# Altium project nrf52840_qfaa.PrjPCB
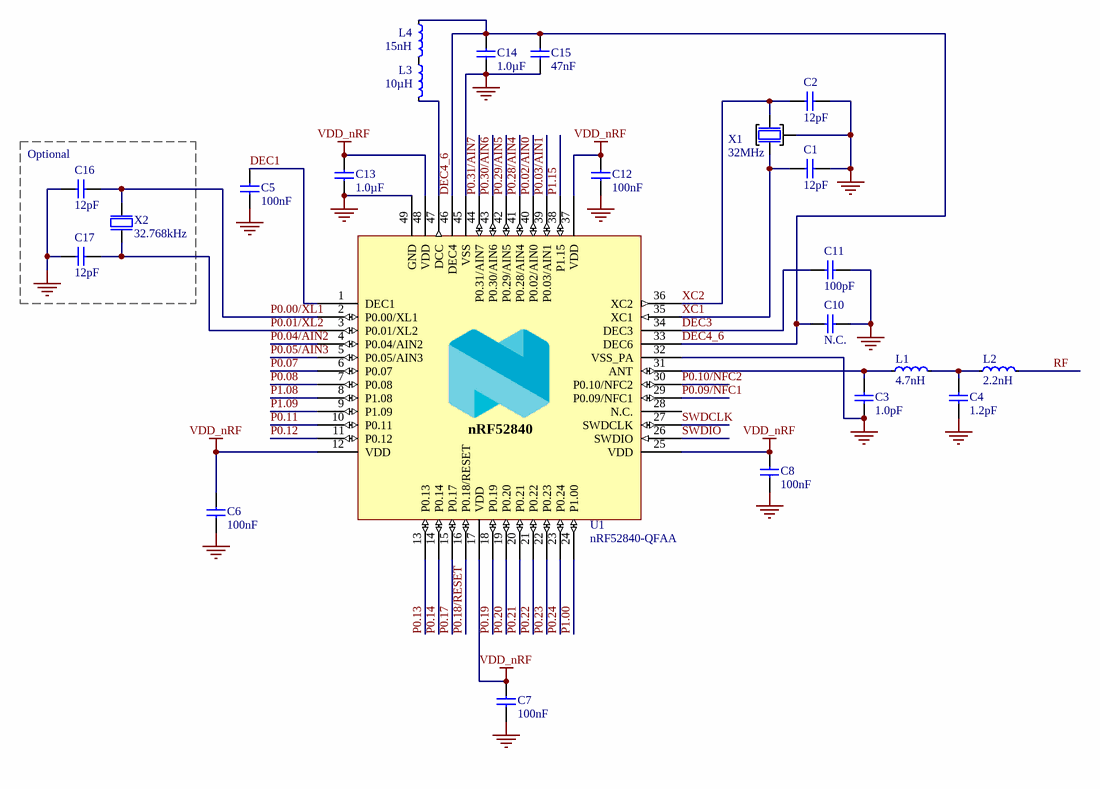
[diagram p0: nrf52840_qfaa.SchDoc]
1 sheet, 23 parts. Net scope: global (net labels, ports and power ports of the same name join across sheets).
Board file: nrf52840_qfaa.PcbDoc

## Sheet nrf52840_qfaa.SchDoc
size A4; Revision: 1.0; SheetNumber: 1; SheetTotal: 1; DrawnBy: RUBR; DocumentSize: A4; Device: nRF52840-QFAA; RefLayoutTitle: Reference Layout

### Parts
C1  12pF  [CAPC0603X03L_C]
C2  12pF  [CAPC0603X03L_C]
C3  1.0pF  [CAPC0603X03L_C]
C4  1.2pF  [CAPC0603X03L_C]
C5  100nF  [CAPC0603X03L_C]
C6  100nF  [CAPC0603X03L_C]
C7  100nF  [CAPC0603X03L_C]
C8  100nF  [CAPC0603X03L_C]
C10  N.C.  [CAPC0603X03L_C_NC]
C11  100pF  [CAPC0603X03L_C]
C12  100nF  [CAPC0603X03L_C]
C13  1.0µF  [CAPC1005X04L]
C14  1.0µF  [CAPC1005X04L]
C15  47nF  [CAPC0603X03L_C]
C16  12pF  [CAPC0603X03L_C]
C17  12pF  [CAPC0603X03L_C]
L1  4.7nH  [INDC0603X03L_C]
L2  2.2nH  [INDC0603X03L_C]
L3  10µH  [INDC1608X06L]
L4  15nH  [INDC1005X04L]
U1  nRF52840-QFAA  [QFN40P600X600X90-48N]
X1  32MHz  [XTAL_2016_NT]
X2  32.768kHz  [XTAL_2012]

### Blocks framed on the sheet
Optional: C16 C17 X2

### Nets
GND: C1.2 C2.2 C3.1 C4.1 C5.2 C6.2 C7.2 C8.2 C10.1 C11.2 C12.2 C13.2 C14.1 C15.2 C16.2 C17.2 U1.32(VSS_PA) U1.45(VSS) U1.49(GND) X1.2(GND)
VDD_nRF: C6.1 C7.1 C8.1 C12.1 C13.1 U1.12(VDD) U1.17(VDD) U1.25(VDD) U1.37(VDD) U1.48(VDD)
DEC1: C5.1 U1.1(DEC1)
DEC3: C11.1 U1.34(DEC3)
DEC4_6: C10.2 C14.2 C15.1 L4.1 U1.33(DEC6) U1.46(DEC4)
P0.00/XL1: C16.1 U1.2(P0.00/XL1) X2.1(inp)
P0.01/XL2: C17.1 U1.3(P0.01/XL2) X2.2(out)
P0.02/AIN0: U1.40(P0.02/AIN0)
P0.03/AIN1: U1.39(P0.03/AIN1)
P0.04/AIN2: U1.4(P0.04/AIN2)
P0.05/AIN3: U1.5(P0.05/AIN3)
P0.07: U1.6(P0.07)
P0.08: U1.7(P0.08)
P0.09/NFC1: U1.29(P0.09/NFC1)
P0.10/NFC2: U1.30(P0.10/NFC2)
P0.11: U1.10(P0.11)
P0.12: U1.11(P0.12)
P0.13: U1.13(P0.13)
P0.14: U1.14(P0.14)
P0.17: U1.15(P0.17)
P0.18/RESET: U1.16(P0.18/RESET)
P0.19: U1.18(P0.19)
P0.20: U1.19(P0.20)
P0.21: U1.20(P0.21)
P0.22: U1.21(P0.22)
P0.23: U1.22(P0.23)
P0.24: U1.23(P0.24)
P0.28/AIN4: U1.41(P0.28/AIN4)
P0.29/AIN5: U1.42(P0.29/AIN5)
P0.30/AIN6: U1.43(P0.30/AIN6)
P0.31/AIN7: U1.44(P0.31/AIN7)
P1.00: U1.24(P1.00)
P1.08: U1.8(P1.08)
P1.09: U1.9(P1.09)
P1.15: U1.38(P1.15)
RF: L2.2
SWDCLK: U1.27(SWDCLK)
SWDIO: U1.26(SWDIO)
XC1: C1.1 U1.35(XC1) X1.1(IN)
XC2: C2.1 U1.36(XC2) X1.3(OUT)
NetC3_2: C3.2 L1.1 U1.31(ANT)
NetC4_2: C4.2 L1.2 L2.1
NetL3_1: L3.1 L4.2
NetL3_2: L3.2 U1.47(DCC)

Not connected (* = marked no-connect by the designer): U1 28(N.C.)

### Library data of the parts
C1 C2 C16 C17 = C0201-12p: Capacitor, NP0, ±2%; Pad Count: 2
C3 = C0201-1.0p: Capacitor, NP0, ±10%; Pad Count: 2
C4 = C0201-1.2p: Capacitor, NP0, ±10%; Pad Count: 2
C5-C8 C12 = C0201-100n: Capacitor, X5R, ±10%; Pad Count: 2
C10 = C0201-N.C.: Not mounted; Assembly: Not mounted; Pad Count: 2
C11 = C0201-100p: Capacitor, NP0, ±5%; Pad Count: 2
C13 C14 = C0402-1µ0: Capacitor, X5R, ±10%; Pad Count: 2
C15 = C0201-47n: Capacitor, X5R, ±10%; Pad Count: 2
L1 = L0201-4n7: High frequency chip inductor ±5%; Pad Count: 2
L2 = L0201-2n2: High frequency chip inductor ±5%; Pad Count: 2
L3 = L0603-10µ-TDK: Chip inductor, IDC,min = 50 mA, ±20%; Pad Count: 2
L4 = L0402-15n: High frequency chip inductor ±10%; Pad Count: 2
U1 = nRF52840-QFAA: Multi-protocol Bluetooth Low Energy, IEEE 802.15.4, ANT and 2.4GHz proprietary system-on-chip; Pad Count: 48
X1 = XTAL_SMD2016_32MHz_8pF_General_NT: XTAL SMD 2016, 32MHz, Cl=8pF, Total Tol: ±30ppm; Pad Count: 4
X2 = XTAL_SMD2012_32.768kHz_9pF_General: XTAL SMD 2012, 32.768kHz, Cl=9pF, Total Tol: ±50ppm; Pad Count: 2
